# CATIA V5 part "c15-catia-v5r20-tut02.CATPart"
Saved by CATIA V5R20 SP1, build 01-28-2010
Part number: Part1
Bounding box of the stored display mesh (mm): x -53 to 53, y -20 to 21, z -12 to 52
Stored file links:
  D:\v5_r20\psrt_files_downloaded\c15-catia-v5r20-prt\c15-catia-v5r20-tut02.CATPart
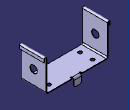
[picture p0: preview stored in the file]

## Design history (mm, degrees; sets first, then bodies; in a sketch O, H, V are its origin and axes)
SheetMetalParameters1: Thickness 1, BendRadius 2, KFactor 0.400515 {= log(min(100,max(20*SheetMetalParameters1.BendRadius,SheetMetalParameters1.Thickness)/SheetMetalParameters1.Thickness))/log(100)/2}, ReliefRadialLength 1, ReliefAxialLength 2, MinimumBendRadius 0
Body1 (main body)
  Sketch1 on xy-plane, origin (0, 0, 0), H (1, 0, 0), V (0, 1, 0)
    line L1 (50, 20) -> (50, -20)
    line L2 (50, -20) -> (-50, -20)
    line L3 (-50, -20) -> (-50, 20)
    line L4 (-50, 20) -> (50, 20)
    length L4 = 100
    length L1 = 40
    vertical: L1 V, L3 V
    horizontal: L2 H, L4 H
    equidistance: L1 L3 O, L2 L4 O
  Wall1: Thickness 1, Profile Sketch1
  Sketch2 on face of Wall1, origin (29.2419, -0.5458, 1), H (1, 0, 0), V (0, 1, 0)
    point P1 (-64.2419, -9.4542)
    reference projected line E1 (-79.2419, -19.4542) -> (-79.2419, 20.5458) from edge [face of Wall1 | face of Wall1]
    reference projected line E2 (20.7581, -19.4542) -> (-79.2419, -19.4542) from edge [face of Wall1 | face of Wall1]
    distance E1 P1 = 15
    distance E2 P1 = 10
  Hole1: placed by Sketch2, at (-35, -10, 1) direction (0, 0, -1), diameter 6, depth 10
  RectPattern1: of Hole1, direction 1 instances 2, spacing 70, along edge [face of Wall1 | face of Wall1] reversed, direction 2 instances 2, spacing 20, along edge [face of Wall1 | face of Wall1]
  Flange1: Angle 90, Length 50, Radius 2, KFacteur 0.400515 {= log(min(100,max(20*Flange1.Radius,SheetMetalParameters1.Thickness)/SheetMetalParameters1.Thickness))/log(100)/2}, Guide edge [face of Wall1 | face of Wall1]
  Flange2: Angle 90, Length 50, Radius 2, KFacteur 0.400515 {= log(min(100,max(20*Flange2.Radius,SheetMetalParameters1.Thickness)/SheetMetalParameters1.Thickness))/log(100)/2}, Guide edge [face of Wall1 | face of Wall1]
  Flange3: Angle 90, Length 5, Radius 1, KFacteur 0.325257 {= log(min(100,max(20*Flange3.Radius,SheetMetalParameters1.Thickness)/SheetMetalParameters1.Thickness))/log(100)/2}, Guide edge [face of Flange2 | face of Flange2]
  Flange4: Angle 90, Length 5, Radius 1, KFacteur 0.325257 {= log(min(100,max(20*Flange4.Radius,SheetMetalParameters1.Thickness)/SheetMetalParameters1.Thickness))/log(100)/2}, Guide edge [face of Flange1 | face of Flange1]
  Sketch3 on face of Flange1, origin (50, 0, 0), H (0, 1, 0), V (0, 0, 1)
    arc A1 centre (0, 25) radius 6 from (-1, 30.9161) to (1, 30.9161) ccw
    point P1 (0, 25)
    line L1 (-1, 30.9161) -> (-1, 29.9161)
    line L2 (-1, 29.9161) -> (1, 29.9161)
    line L3 (1, 29.9161) -> (1, 30.9161)
    radius A1 = 6
    distance H P1 = 25
    length L2 = 2
    distance V L1 = 1
    length L3 = 1
    coincidence: P1 V
    vertical: L1 V, L3 V
    horizontal: L2 H
  CutOut1: Direction Sketch3, EndLimit through (limit type 3), Orientation true, Profile Sketch3, StartLimit through (limit type 2)
  d_NewWallOnEdge1: NewWallOnEdge_Edge edge [face of Wall1 | face of Wall1], NewWallOnEdge_Length 13, NewWallOnEdge_HeightLimitOffset 0, NewWallOnEdge_WidthOffset1 -41, NewWallOnEdge_WidthOffset2 -41, NewWallOnEdge_Angle 90, NewWallOnEdge_BendRadiusValue 2 {= SheetMetalParameters1.BendRadius}, KFacteur 0.400515 {= log(min(100,max(20*d_NewWallOnEdge1.Radius,SheetMetalParameters1.Thickness)/SheetMetalParameters1.Thickness))/log(100)/2}
  Corner1: CornerRadius 3, CornerChamferEdges (edge [face of d_NewWallOnEdge1 | face of d_NewWallOnEdge1]; edge [face of d_NewWallOnEdge1 | face of d_NewWallOnEdge1])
